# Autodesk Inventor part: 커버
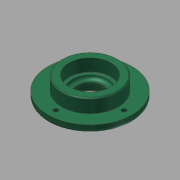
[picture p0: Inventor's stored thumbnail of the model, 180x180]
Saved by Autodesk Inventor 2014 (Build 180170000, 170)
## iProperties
Company: 한국ATC센터
Created: 2014-10
Part Number: 커버
Document SubType Name: Modeling
Designer: KYOUNG IL JANG
Density: 7.86 g/cm^3
Mass: 351.567 g
Surface Area: 161.165 cm^2
Volume: 44.7286 cm^3
Material: 강철, 연강
Appearance: 강철
d0: 80.000 mm
d1: 7.000 mm
d2: 0.00 deg
d3: 54.000 mm
d4: 13.000 mm
d5: 0.00 deg
d6: 40.000 mm
d7: 5.000 mm
d8: 0.00 deg
d11: 25.000 mm
d13: 32.000 mm
d14: 8.300 mm
d20: 34.000 mm
d22: 40.000 mm
d23: 12.000 mm
d25: 3.000 mm
d27: 0.300 mm
d28: 1.000 mm
d31: 1.200 mm
d33: 30.00 deg
d34: 3.000 mm
d35: 65.000 mm
d36: 4.500 mm
d38: 8.000 mm
d39: 4.400 mm
d43: 4.000 ul
d44: 360.00 deg
Author: KYOUNG IL JANG
Revision Number: 1
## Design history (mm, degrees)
sketch "스케치1"
  geometry: C1 r 40 at (0, 0); 1 further point
  constraints: 1 centre point, 1 coincident
  dimensions: "d0" = 80 diameter of C1
extrude "돌출1" new body sketch "스케치1" distance "d1" = 7; taper "d2" = 0 deg
sketch "스케치2"
  geometry: C1 r 27 at (0, 0); 1 further point
  constraints: 1 centre point, 1 coincident
  dimensions: "d3" = 54 diameter of C1
extrude "돌출2" join sketch "스케치2" distance "d4" = 13; taper "d5" = 0 deg
sketch "스케치3"
  geometry: C1 r 20 at (0, 0); 1 further point
  constraints: 1 centre point, 1 coincident
  dimensions: "d6" = 40 diameter of C1
extrude "돌출3" join sketch "스케치3" distance "d7" = 5; taper "d8" = 0 deg
hole "구멍1" diameter "d11" = 25; stored, may be unused: countersink angle "d15" = 90 deg, drill point angle "d17" = 118 deg; dims "d9" = 10, "d10" = 10, "d12" = 6, "d13" = 32, "d14" = 8.3, "d16" = 8
hole "구멍2" diameter "d20" = 34; stored, may be unused: countersink angle "d24" = 90 deg, drill point angle "d26" = 0 deg; dims "d18" = 10, "d19" = 10, "d21" = 6, "d22" = 40, "d23" = 12, "d25" = 3
fillet "모깎기2" dims "d34" = 3
fillet "모깎기1" dims "d27" = 0.3
chamfer "모따기1" distance "d28" = 1; stored, may be unused: second distance "d29" = 2, angle "d30" = 45 deg
chamfer "모따기2" distance "d31" = 1.2; stored, may be unused: second distance "d32" = 2, angle "d33" = 30 deg
sketch "스케치4" dims "d35" = 65
  geometry: 3 further points
  constraints: 2 horizontal alignment, 1 coincident, 2 other
hole "구멍3" sketch "스케치4" at (32.5, 0) diameter "d36" = 4.5; stored, may be unused: countersink angle "d40" = 90 deg, drill point angle "d42" = 118 deg; dims "d37" = 6, "d38" = 8, "d39" = 4.4, "d41" = 13
node "솔리드1"
pattern_circular "원형 패턴1" dims count "d43" = 4, angle "d44" = 360 deg
